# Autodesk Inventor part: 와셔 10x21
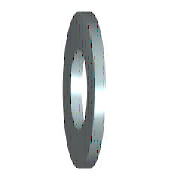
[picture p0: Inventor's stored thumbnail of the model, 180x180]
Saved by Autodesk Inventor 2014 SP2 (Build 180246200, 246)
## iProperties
Created: 2012-02
Part Number: 와셔 10x21
Material: 강철, 연강
Description: 평면 와셔
Document SubType Name: Modeling
Standard: KS B 1326
Designer: mduedu
Standards Organization: KS
Language: ko-KR
Size Designation: 10x21
Categories: <MemberInstance><Categories><Category DisplayName="조임쇠" InternalName="e4da775c-781d-43d5-af7c-5136215cf5a6" Mnemonic="FSTN"><Category DisplayName="와셔" InternalN
Density: 1 g/cm^3
Appearance: 파란색 - 벽 페인트 - 광택
IsCustomPart: 1
Author: mduedu
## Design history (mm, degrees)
sketch "스케치"
  geometry: C1 r 10.5 at (0, 0); C2 r 5.25 at (0, 0); 1 further point
  constraints: 2 centre point, 2 coincident
  dimensions: "d0" = 10.5 diameter of C2 (= SD1); "d1" = 21 diameter of C1 (= SD2)
extrude "본체" new body sketch "스케치" distance "d2" = 2 (= SD); taper "d3" = 0 deg
workaxis "Work Axis1"
workplane "Work Plane1"
body "Solid1"
other parameters: "SD1" = 10.5 [user parameter; used in 1 equation term], "SD2" = 21 [user parameter; used in 1 equation term], "SD" = 2 [user parameter; used in 1 equation term], "d4" = 0, "d5" = 0, "d6" = 0, "d7" = 0
